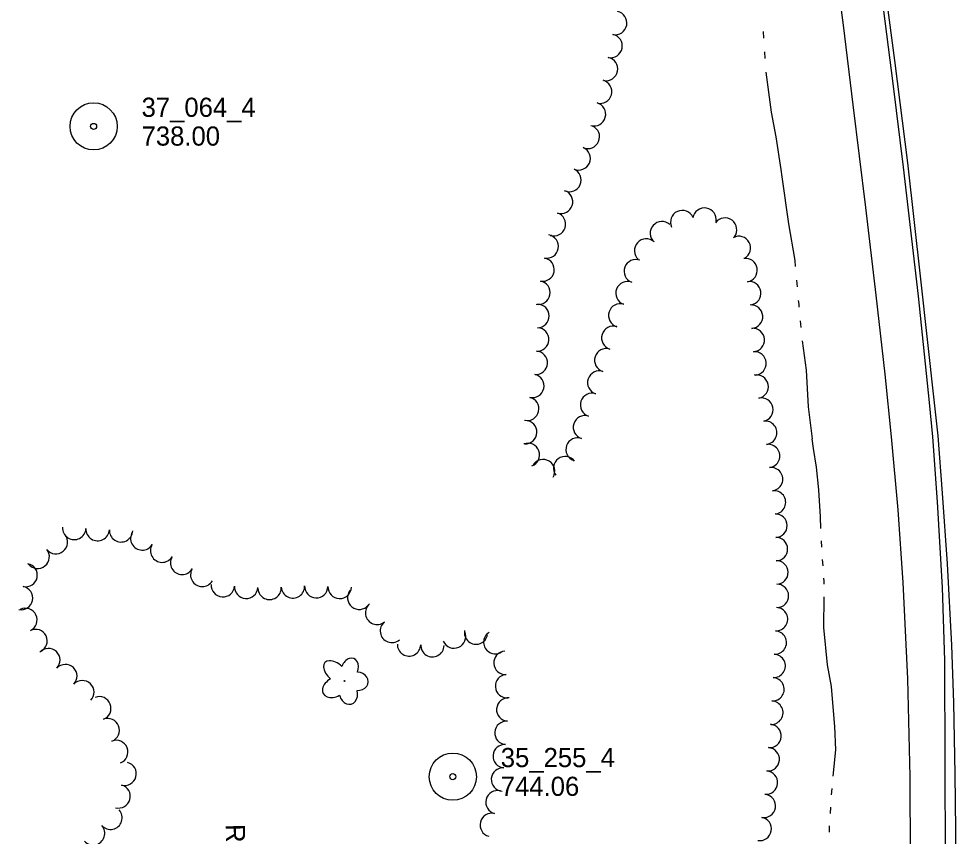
# Model space of a CAD drawing. Extents: x 589250 to 1188077, y 162953 to 363065.
# Drawn here: x 593855.5 to 594148.7, y 165342.4 to 165598.1 of the extents above; entities that cross this region are included whole.
import ezdxf

# ---------------------------------------------------------------- set-up
doc = ezdxf.new("R2010")
doc.units = 0
for name, color, linetype in [('E_BLD_Text', 7, 'Continuous'), ('E_LAND_TreeLine_P', 7, 'Continuous'), ('E_LAND_Vegetation', 7, 'Continuous'), ('E_MAP_PassPoints', 7, 'Continuous'), ('E_RDWY', 7, 'Continuous'), ('E_RDWY_Gravel', 7, 'Continuous'), ('E_WTR_FlowLine', 7, 'Continuous')]:
    doc.layers.add(name, color=color, linetype=linetype)

msp = doc.modelspace()

# ---------------------------------------------------------------- linework, layer by layer
at = {"layer": 'E_LAND_TreeLine_P'}
for centre, radius, start, end in [((594042.01, 165596.78), 3.67, 258.7777, 78.7777), ((594040.58, 165589.59), 3.67, 258.7777, 78.7777), ((594039.15, 165582.4), 3.67, 258.7777, 78.7777), ((594037.3, 165575.3), 3.67, 254.8797, 74.8797), ((594035.38, 165568.23), 3.67, 254.8797, 74.8797), ((594033.46, 165561.15), 3.67, 246.9061, 66.9061), ((594030.58, 165554.41), 3.67, 246.9061, 66.9061), ((594027.7, 165547.66), 3.67, 246.9061, 66.9061), ((594025.09, 165540.82), 3.67, 252.1945, 72.1945), ((594022.85, 165533.84), 3.67, 252.1945, 72.1945), ((594062.99, 165534.48), 3.67, 24.5487, 204.5487), ((594069.97, 165535.25), 3.67, 350.9126, 170.9126), ((594056.63, 165531), 3.67, 47.6823, 227.6823), ((594076.37, 165532.11), 3.67, 323.3514, 143.3514), ((594020.61, 165526.86), 3.67, 259.6813, 79.6813), ((594051.7, 165525.58), 3.67, 47.6823, 227.6823), ((594080.71, 165526.39), 3.67, 298.4998, 118.4998), ((594019.3, 165519.64), 3.67, 259.6813, 79.6813), ((594048.47, 165519.11), 3.67, 69.2822, 249.2822), ((594082.8, 165519.47), 3.67, 278.8895, 98.8895), ((594017.99, 165512.43), 3.67, 259.6813, 79.6813), ((594045.87, 165512.26), 3.67, 69.2822, 249.2822), ((594083.93, 165512.23), 3.67, 278.8895, 98.8895), ((594017.71, 165505.13), 3.67, 270.4109, 90.4109), ((594043.61, 165505.28), 3.67, 72.6734, 252.6734), ((594084.5, 165504.92), 3.67, 274.2059, 94.2059), ((594017.62, 165497.8), 3.67, 266.5865, 86.5865), ((594041.43, 165498.28), 3.67, 72.6734, 252.6734), ((594085.04, 165497.61), 3.67, 274.2059, 94.2059), ((594017.18, 165490.48), 3.67, 266.5865, 86.5865), ((594039.24, 165491.28), 3.67, 72.6734, 252.6734), ((594085.57, 165490.29), 3.67, 274.2059, 94.2059), ((594016.09, 165483.25), 3.67, 257.4987, 77.4987), ((594037.04, 165484.29), 3.67, 72.1006, 252.1006), ((594086.24, 165483), 3.67, 281.6372, 101.6372), ((594034.79, 165477.31), 3.67, 72.1006, 252.1006), ((594014.5, 165476.09), 3.67, 257.4987, 77.4987), ((594087.72, 165475.82), 3.67, 281.6372, 101.6372), ((594013.87, 165468.81), 3.67, 267.3359, 87.3359), ((594032.57, 165470.32), 3.67, 72.5721, 252.5721), ((594088.92, 165468.6), 3.66, 277.2437, 97.2437), ((594030.29, 165463.35), 3.67, 70.6245, 250.6245), ((594014.7, 165461.66), 3.67, 290.3205, 110.3205), ((594089.84, 165461.34), 3.66, 277.2437, 97.2437), ((594019.46, 165456.61), 3.67, 328.7309, 148.7309), ((594026.39, 165457.52), 3.67, 36.3421, 216.3421), ((594090.77, 165454.08), 3.66, 277.2437, 97.2437), ((594091.69, 165446.82), 3.66, 277.2437, 97.2437), ((594092.14, 165439.53), 3.66, 271.1978, 91.1978), ((593867.13, 165434.37), 3.66, 218.7299, 38.7299), ((593872.87, 165438.83), 3.66, 177.0649, 357.0649), ((593880.18, 165438.46), 3.66, 177.0649, 357.0649), ((593887.49, 165438.08), 3.66, 177.0649, 357.0649), ((593894.13, 165435.55), 3.66, 148.2867, 328.2867), ((594092.29, 165432.21), 3.66, 271.1978, 91.1978), ((593861.42, 165429.8), 3.66, 218.7299, 38.7299), ((593900.35, 165431.71), 3.66, 148.2867, 328.2867), ((593906.59, 165427.89), 3.66, 149.3705, 329.3705), ((594092.45, 165424.9), 3.66, 271.1978, 91.1978), ((593857.63, 165424.05), 3.66, 258.8087, 78.8087), ((593912.89, 165424.16), 3.66, 149.3705, 329.3705), ((593856.21, 165416.88), 3.66, 258.8087, 78.8087), ((593919.33, 165420.91), 3.66, 176.06, 356.06), ((593926.63, 165420.41), 3.66, 176.06, 356.06), ((593933.93, 165420.08), 3.66, 183.5879, 3.5879), ((593941.23, 165420.53), 3.66, 183.5879, 3.5879), ((593948.54, 165420.59), 3.66, 178.2952, 358.2952), ((593955.86, 165420.37), 3.66, 178.2952, 358.2952), ((593961.99, 165417), 3.66, 140.6986, 320.6986), ((594092.6, 165417.58), 3.66, 271.1978, 91.1978), ((593857.57, 165410.05), 3.66, 295.6473, 115.6473), ((593967.56, 165412.27), 3.66, 129.338, 309.338), ((594092.31, 165410.27), 3.66, 267.1409, 87.1409), ((593972.2, 165406.61), 3.66, 129.338, 309.338), ((593860.73, 165403.45), 3.66, 295.6473, 115.6473), ((593991.61, 165404.87), 3.66, 203.6041, 23.6041), ((593998.52, 165406.09), 3.66, 169.7243, 349.7243), ((594004.54, 165403.07), 3.66, 121.1908, 301.1908), ((594091.94, 165402.97), 3.66, 267.1409, 87.1409), ((593977.55, 165402.4), 3.66, 178.1095, 358.1095), ((593984.86, 165402.16), 3.66, 178.1095, 358.1095), ((593864.76, 165397.48), 3.66, 316.613, 136.613), ((594007.71, 165396.62), 3.66, 93.8735, 273.8735), ((594091.58, 165395.66), 3.66, 267.1409, 87.1409), ((593870.07, 165392.46), 3.66, 316.613, 136.613), ((594008.2, 165389.32), 3.66, 93.8735, 273.8735), ((593875.39, 165387.43), 3.66, 316.613, 136.613), ((594091.21, 165388.35), 3.66, 267.1409, 87.1409), ((593880.69, 165382.39), 3.66, 291.197, 111.197), ((594008.58, 165382.02), 3.66, 85.7068, 265.7068), ((594090.85, 165381.04), 3.66, 267.1409, 87.1409), ((593883.33, 165375.57), 3.66, 291.197, 111.197), ((594008.03, 165374.72), 3.66, 85.7068, 265.7068), ((594090.29, 165373.75), 3.66, 265.5405, 85.5405), ((593885.98, 165368.74), 3.66, 291.197, 111.197), ((594007.48, 165367.43), 3.66, 85.7068, 265.7068), ((594089.72, 165366.45), 3.66, 265.5405, 85.5405), ((593888.61, 165361.92), 3.66, 255.0782, 75.0782), ((594006.93, 165360.13), 3.66, 85.7068, 265.7068), ((594089.15, 165359.16), 3.66, 265.5405, 85.5405), ((593886.73, 165354.85), 3.66, 255.0782, 75.0782), ((594005.21, 165353.02), 3.66, 75.7611, 255.7611), ((594088.51, 165351.87), 3.66, 259.9627, 79.9627), ((593884.19, 165348.18), 3.66, 221.885, 41.885), ((594003.41, 165345.93), 3.66, 75.7611, 255.7611), ((594087.23, 165344.67), 3.66, 259.9627, 79.9627), ((593878.74, 165343.3), 3.66, 221.885, 41.885)]:
    msp.add_arc(centre, radius, start, end, dxfattribs=at)
at = {"layer": 'E_LAND_Vegetation'}
msp.add_circle((593957.38, 165390.94), 0.128, dxfattribs=at)
for centre, major_axis, ratio in [((593954.77, 165393.54), (3.5, -3.21), 0.560249), ((593959, 165394.61), (-1.27, -3.4), 0.716896), ((593961.36, 165390.83), (-3.45, 0.09), 0.832022), ((593954.41, 165389.03), (3.69, 2.04), 0.691916), ((593958.55, 165387.22), (-0.94, 3.49), 0.782863)]:
    msp.add_ellipse(centre, major_axis=major_axis, ratio=ratio, start_param=1.570796, end_param=4.712389, dxfattribs=at)
at = {"layer": 'E_MAP_PassPoints'}
for centre, radius in [((593878.91, 165564.43), 7.38), ((593878.91, 165564.43), 7.38), ((593878.91, 165564.43), 7.38), ((593878.91, 165564.43), 7.38), ((593878.91, 165564.43), 0.945), ((593878.91, 165564.43), 0.945), ((593878.91, 165564.43), 0.945), ((593878.91, 165564.43), 0.945), ((593991.24, 165361.02), 7.38), ((593991.24, 165361.02), 7.38), ((593991.24, 165361.02), 7.38), ((593991.24, 165361.02), 7.38), ((593991.24, 165361.02), 0.945), ((593991.24, 165361.02), 0.945), ((593991.24, 165361.02), 0.945), ((593991.24, 165361.02), 0.945)]:
    msp.add_circle(centre, radius, dxfattribs=at)
at = {"layer": 'E_RDWY'}
for p, q in [((594113.39, 165596.08), (594109.6, 165625.99)), ((594123.77, 165617.33), (594128.89, 165577.83)), ((594116.44, 165571.2), (594113.39, 165596.08)), ((594128.89, 165577.83), (594132.12, 165551.63)), ((594120.42, 165539.01), (594116.44, 165571.2)), ((594132.12, 165551.63), (594136.72, 165511.29)), ((594123.68, 165511.67), (594120.42, 165539.01)), ((594126.41, 165486.96), (594123.68, 165511.67)), ((594136.72, 165511.29), (594140.22, 165478.09)), ((594128.47, 165467.32), (594126.41, 165486.96)), ((594140.22, 165478.09), (594141.2, 165467.35)), ((594130.49, 165444.48), (594128.47, 165467.32)), ((594141.2, 165467.35), (594142.75, 165446.95)), ((594142.75, 165446.95), (594144.3, 165420.19)), ((594132.07, 165421.77), (594130.49, 165444.48)), ((594133.53, 165391.67), (594132.07, 165421.77)), ((594144.3, 165420.19), (594145.02, 165397.35)), ((594145.02, 165397.35), (594145.09, 165365.2)), ((594134.29, 165360.98), (594133.53, 165391.67)), ((594145.09, 165365.2), (594145.23, 165329.35)), ((594134.4, 165327.93), (594134.29, 165360.98))]:
    msp.add_line(p, q, dxfattribs=at)
at = {"layer": 'E_RDWY_Gravel'}
for p, q in [((594123.45, 165629.65), (594129.32, 165585.05)), ((594129.32, 165585.05), (594133.39, 165553.07)), ((594133.39, 165553.07), (594137.54, 165516.65)), ((594137.54, 165516.65), (594141.7, 165478.88)), ((594141.7, 165478.88), (594142.87, 165467.6)), ((594142.87, 165467.6), (594144.32, 165449.75)), ((594144.32, 165449.75), (594145.85, 165427.64)), ((594145.85, 165427.64), (594147.22, 165402.15)), ((594147.22, 165402.15), (594147.85, 165384.08)), ((594147.85, 165384.08), (594148.23, 165361.77)), ((594148.23, 165361.77), (594148.67, 165325.73))]:
    msp.add_line(p, q, dxfattribs=at)
at = {"layer": 'E_WTR_FlowLine'}
for p, q in [((594088.3, 165594.1), (594088.42, 165591.98)), ((594088.67, 165587.74), (594088.79, 165585.62)), ((594089.16, 165581.4), (594090.79, 165568.86)), ((594090.79, 165568.86), (594092.3, 165561.13)), ((594092.3, 165561.13), (594093.78, 165550.99)), ((594093.78, 165550.99), (594094.13, 165548.65)), ((594094.13, 165548.65), (594096.23, 165533.98)), ((594096.23, 165533.98), (594098.18, 165522.47)), ((594098.18, 165522.47), (594098.35, 165520.56)), ((594098.73, 165516.33), (594098.91, 165514.22)), ((594099.29, 165509.99), (594099.4, 165508.82)), ((594099.4, 165508.82), (594099.48, 165507.88)), ((594099.86, 165503.65), (594100.06, 165501.54)), ((594100.47, 165497.31), (594101.7, 165488.18)), ((594101.7, 165488.18), (594102.35, 165476.7)), ((594102.35, 165476.7), (594103.61, 165466.72)), ((594104.02, 165463.69), (594103.61, 165466.72)), ((594104.93, 165457.86), (594104.02, 165463.69)), ((594105.71, 165450.76), (594104.93, 165457.86)), ((594106.21, 165442.31), (594105.71, 165450.76)), ((594106.35, 165438.67), (594106.21, 165442.31)), ((594106.64, 165432.84), (594106.51, 165434.78)), ((594107.03, 165427.02), (594106.9, 165428.96)), ((594107.36, 165422.18), (594107.29, 165423.14)), ((594107.35, 165421.19), (594107.36, 165422.18)), ((594107.27, 165407.68), (594107.33, 165417.3)), ((594108.38, 165396.04), (594107.27, 165407.68)), ((594109.69, 165389.27), (594108.38, 165396.04)), ((594109.71, 165389.15), (594109.69, 165389.27)), ((594110.75, 165376.72), (594109.71, 165389.15)), ((594111.05, 165369.45), (594110.75, 165376.72)), ((594110.22, 165361.15), (594111.05, 165369.45)), ((594109.68, 165355.34), (594109.86, 165357.28)), ((594109.3, 165349.51), (594109.42, 165351.46)), ((594109.01, 165343.69), (594109.05, 165345.49)), ((594109.05, 165345.49), (594109.06, 165345.63))]:
    msp.add_line(p, q, dxfattribs=at)

# ---------------------------------------------------------------- texts
at = {"layer": 'E_BLD_Text'}
msp.add_text('RUINS', height=6, rotation=270.4812, dxfattribs=at).set_placement((593920.25, 165346.18))
at = {"layer": 'E_MAP_PassPoints'}
for s, p in [('37_064_4', (593893.91, 165567.41)), ('37_064_4', (593893.91, 165567.41)), ('37_064_4', (593893.91, 165567.41)), ('37_064_4', (593893.91, 165567.41)), ('738.00', (593893.91, 165558.41)), ('738.00', (593893.91, 165558.41)), ('738.00', (593893.91, 165558.41)), ('738.00', (593893.91, 165558.41)), ('35_255_4', (594006.24, 165364.01)), ('35_255_4', (594006.24, 165364.01)), ('35_255_4', (594006.24, 165364.01)), ('35_255_4', (594006.24, 165364.01)), ('744.06', (594006.24, 165355.01)), ('744.06', (594006.24, 165355.01)), ('744.06', (594006.24, 165355.01)), ('744.06', (594006.24, 165355.01))]:
    msp.add_text(s, height=6, dxfattribs=at).set_placement(p)

doc.saveas('drawing.dxf')
